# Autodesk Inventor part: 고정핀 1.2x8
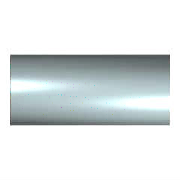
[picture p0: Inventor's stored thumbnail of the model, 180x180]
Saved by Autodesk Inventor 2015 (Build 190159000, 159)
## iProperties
IsCustomPart: 1
Created: 2012-02
Part Number: 고정핀 1.2x8
Material: 강철, 연강
Description: 평행 핀
Document SubType Name: Modeling
Standard: KS B 1320
Designer: P15F
Standards Organization: KS
Language: ko-KR
Size Designation: C 1.2 x  8
Categories: <MemberInstance><Categories><Category DisplayName="조임쇠" InternalName="e4da775c-781d-43d5-af7c-5136215cf5a6" Mnemonic="FSTN"><Category DisplayName="핀" InternalNa
Density: 1 g/cm^3
Appearance: 노란색
Author: P15F
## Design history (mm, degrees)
sketch "스케치1"
  geometry: C1 r 0.6 at (0, 0); 1 further point
  constraints: 1 centre point, 1 coincident
  dimensions: "d1" = 1.2 diameter of C1 (= NND)
extrude "본체" new body sketch "스케치1" distance "d2" = 8 (= NLG); taper "d3" = 0 deg
node "작업 평면1"
node "작업 평면2"
body "Solid1"
other parameters: "NND" = 1.2 [user parameter; used in 1 equation term], "NLG" = 8 [user parameter; used in 1 equation term], "d8" = 0, "d9" = 0, "d10" = 0
